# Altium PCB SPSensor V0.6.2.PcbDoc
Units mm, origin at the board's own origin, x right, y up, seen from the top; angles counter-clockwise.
Board outline 97.48 x 57.45 mm, 2 copper layers (TopLayer, BottomLayer), stack 1.671 mm thick; 103 components, 64 nets, 347 pads, 160 vias.
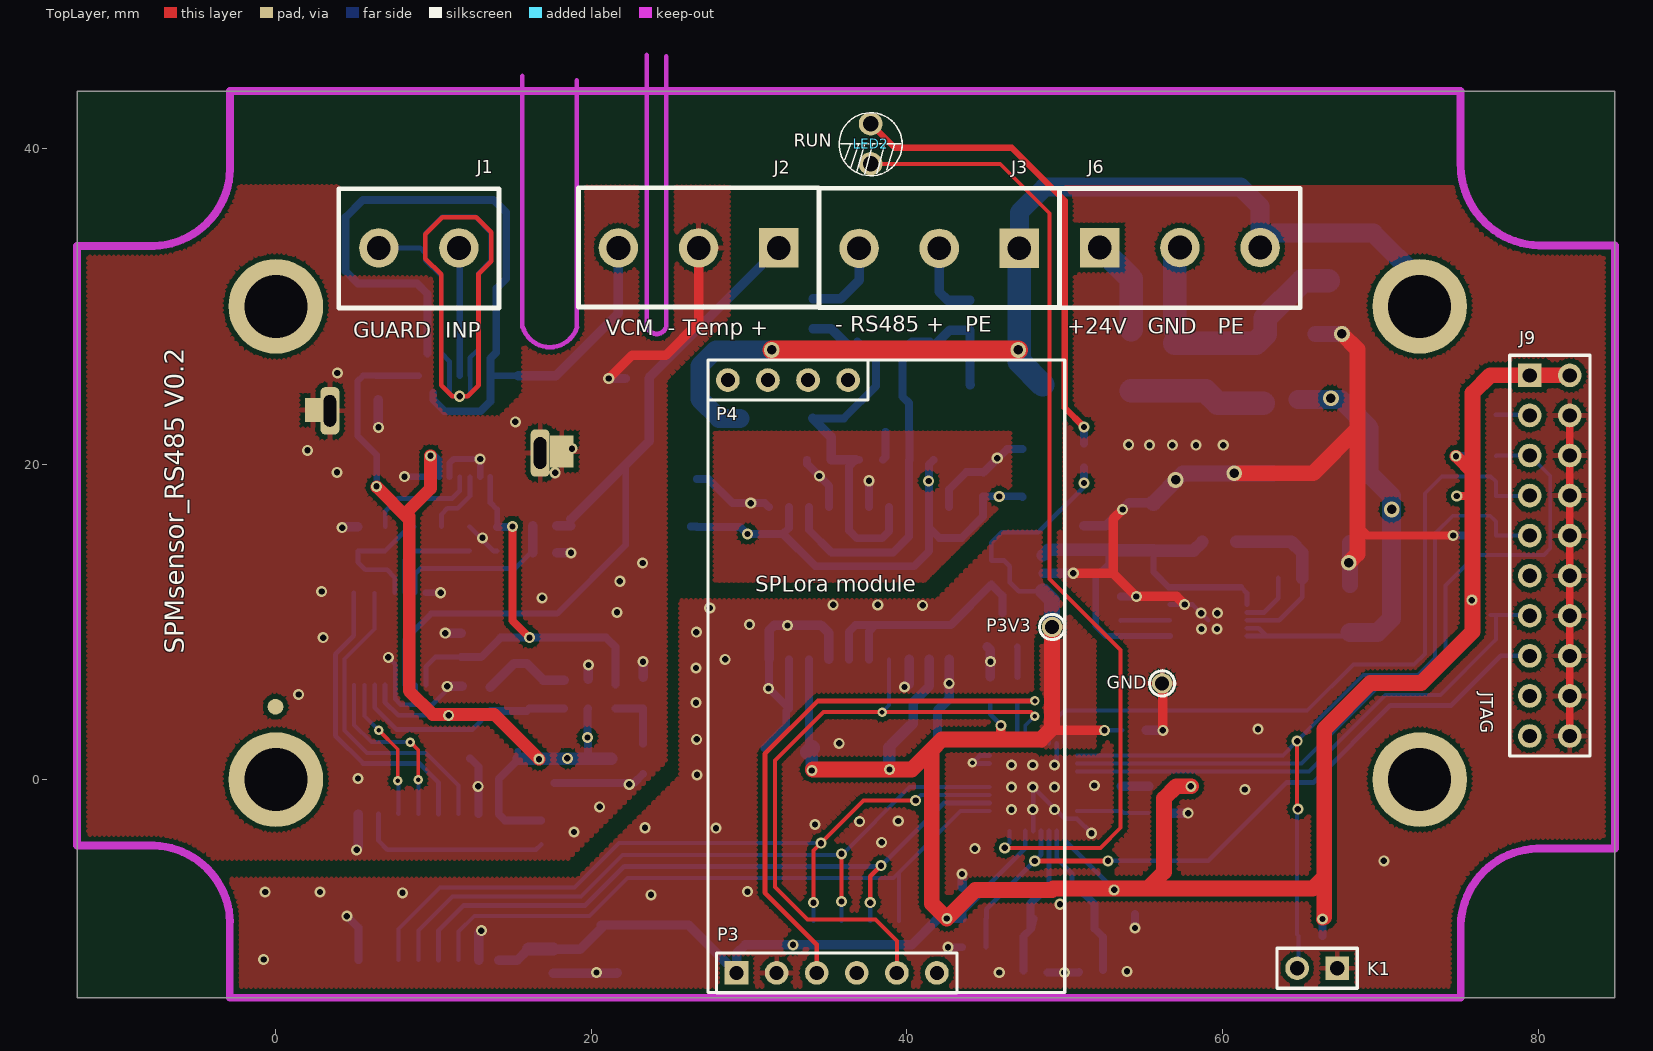
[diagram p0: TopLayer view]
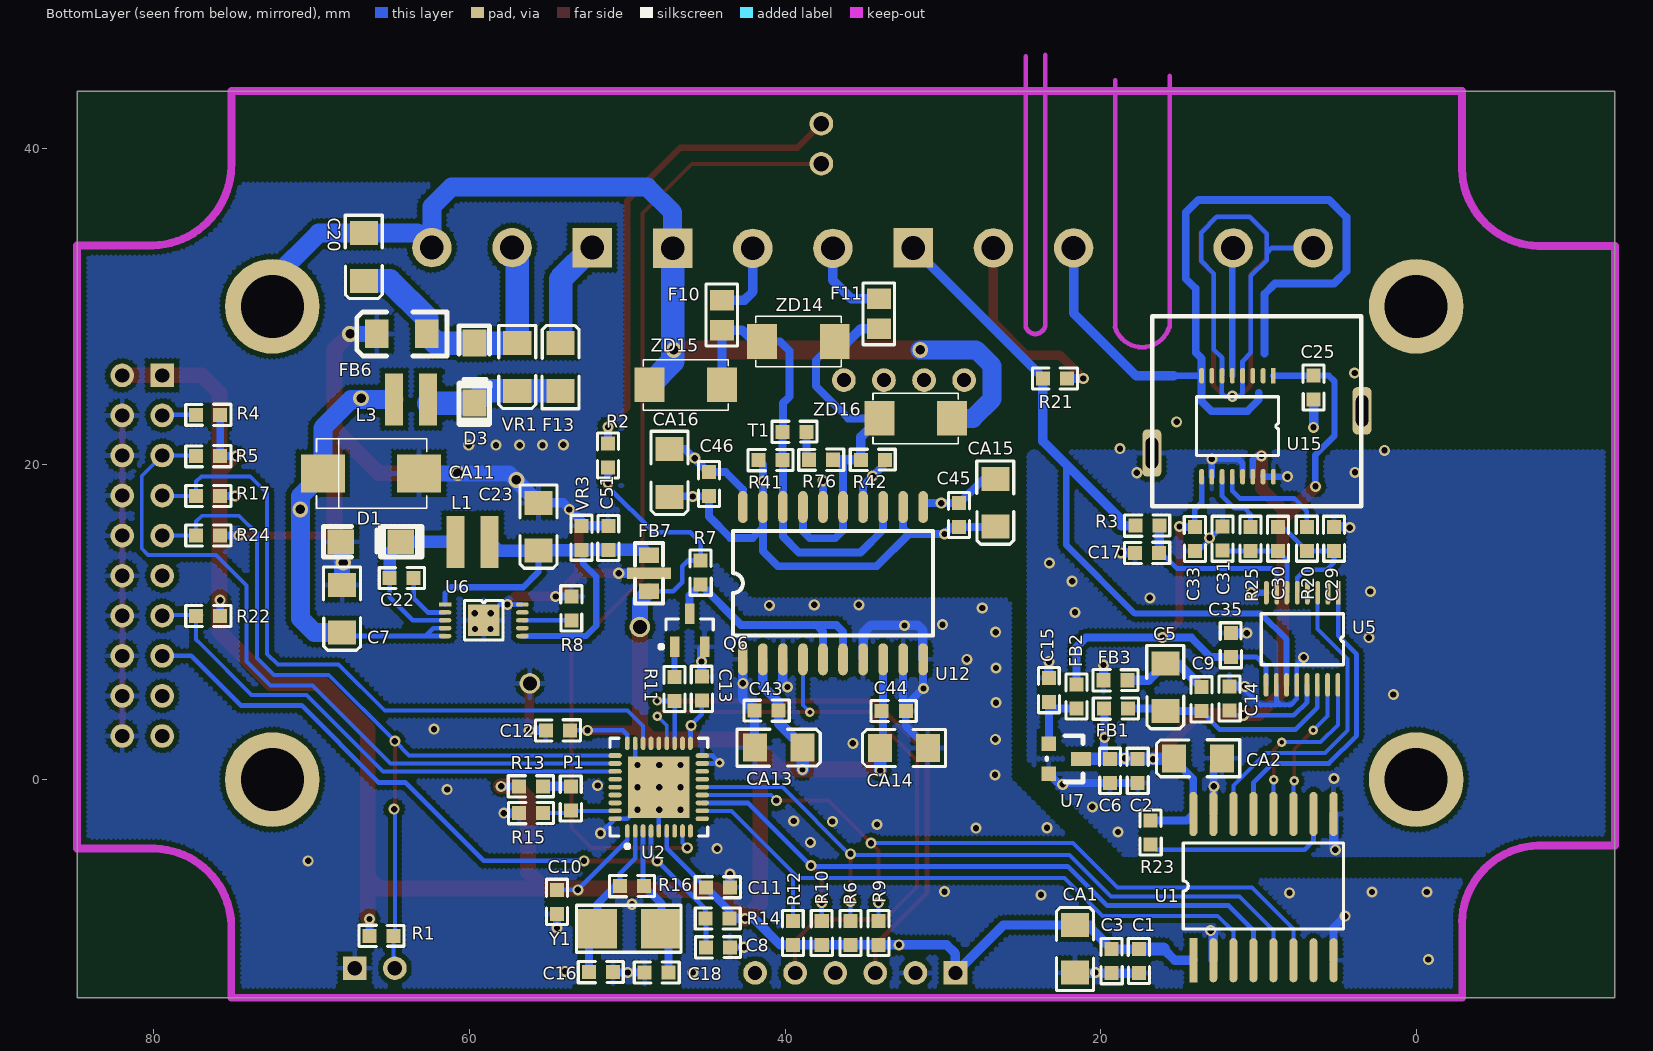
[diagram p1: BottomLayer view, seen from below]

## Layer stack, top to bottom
TopLayer: signal copper 0.0356
Dielectric: core 1.6, FR-4, Dk 4.8
BottomLayer: signal copper 0.0356

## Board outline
-12.6,-13.825 84.875,-13.825 84.875,43.625 -12.6,43.625

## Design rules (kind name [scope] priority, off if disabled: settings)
Clearance Clearance_poly [InPolygon] p1: gap=0.3
Clearance [All] p2: gap=0.15
ComponentClearance [All] p1: gap=0.15 collisioncheckmode=3 verticalgap=0.254 showdistances=FALSE
FabricationTestPointUsage TestPointUsage [All] p1: valid=0 allowmultiple=FALSE
FabricationTestpoint Testpoint [All] p1: side=3 testpointundercomponent=TRUE minsize=1.016 maxsize=2.54 preferedsize=1.524 minholesize=0.508 maxholesize=1.016 preferedholesize=0.813 testpointgrid=0.025 allowsidetop=TRUE allowsidebottom=TRUE usegrid=TRUE gridtolerance=0
HoleSize [All] p1: absolutevalues=TRUE maxlimit=10 minlimit=0.025 maxpercent=80.000 minpercent=20.000
MinimumSolderMaskSliver [All] p1: minsoldermaskwidth=0.15
PlaneClearance [All] p1: clearance=0.2
PlaneConnect [All] p1: planeconnectstyle=Relief reliefexpansion=0.3 reliefentries=4 reliefconductorwidth=0.3 reliefairgap=0.3
PolygonConnect PolygonConnect_via [IsVia] p1: connectstyle=Direct reliefconductorwidth=0.254 reliefentries=4 polygonreliefangle="90 Angle"
PolygonConnect [All] p2: connectstyle=Relief reliefconductorwidth=0.3 reliefentries=4 polygonreliefangle="90 Angle"
RoutingVias [All] p1: holewidth=0.305 width=0.61 viastyle="Through Hole" minholewidth=0.254 minwidth=0.508 maxholewidth=2 maxwidth=5
SilkToSilkClearance [All] p1: silktosilkclearance=0
SilkscreenOverComponentPads [All] p1: minsilkscreentomaskgap=0
SolderMaskExpansion [All] p1: expansion=0.102
Width [All] p1: maxlimit=5.08 minlimit=0.1 preferedwidth=0.254
19 further rules are at their usual default settings.

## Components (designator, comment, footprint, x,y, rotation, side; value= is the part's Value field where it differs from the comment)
C1 "10nF" SM0603 17.525,-11.5 r270 bottom
C2 "0.1uF" SM0603 17.6,0.55 r270 bottom
C3 "0.1uF" SM0603 19.35,-11.5 r90 bottom
C5 "10uF" SM1206 15.9,5.85 r270 bottom
C6 "4.7uF" SM0603 19.35,0.55 r270 bottom
C7 "4.7uF/50V" SM1206 68.075,10.825 r270 bottom
C8 "0.1uF" SM0603 44.25,-10.575 r180 bottom
C9 "0.1uF" SM0603 13.65,5.1 r90 bottom
C10 "0.1uF" SM0603 54.405,-7.75 r270 bottom
C11 "0.1uF" SM0603 44.255,-6.775 r180 bottom
C12 "0.1uF" SM0603 54.4,3.075 r0 bottom
C13 "0.1uF" SM0603 45.33,5.765 r90 bottom
C14 "0.1uF" SM0603 11.875,5.15 r90 bottom
C15 "1uF" SM0603 23.325,5.675 r90 bottom
C16 "22pF" SM0603 51.675,-12.15 r180 bottom
C17 "1uF" SM0603 17.055,14.325 r0 bottom
C18 "22pF" SM0603 48.14,-12.275 r0 bottom
C20 "1nF/2kV" SM1206 66.7,33.125 r270 bottom
C22 "0.47uF" SM0603 64.3,12.725 r0 bottom
C23 "22uF" SM1206 55.625,16.025 r270 bottom
C25 "0.1uF" SM0603 6.45,24.85 r270 bottom
C29 "1uF" SM0603 5.15,15.26 r270 bottom
C30 "100pF" SM0603 8.7,15.26 r270 bottom
C31 "1uF" SM0603 12.325,15.275 r90 bottom
C33 "0.1uF" SM0603 13.975,15.25 r270 bottom
C35 "0.1uF" SM0603 11.8,8.525 r90 bottom
C43 "0.1uF" SM0603 41.175,4.325 r0 bottom
C44 "0.1uF" SM0603 33.11,4.4 r180 bottom
C45 "0.1uF" SM0603 29.025,16.775 r90 bottom
C46 "0.1uF" SM0603 44.775,18.725 r270 bottom
C51 "0.1uF" SM0603 51.25,15.325 r90 bottom
CA1 "10uF" SM1206 21.625,-10.725 r90 bottom
CA2 "10uF" SM1206 13.825,1.35 r0 bottom
CA11 "47uF/50V" D 69.3,19.4 r180 bottom
CA13 "10uF" SM1206 40.4,2.025 r180 bottom
CA14 "10uF" SM1206 32.465,2 r0 bottom
CA15 "10uF" SM1206 26.675,17.55 r270 bottom
CA16 "10uF" SM1206 47.325,19.435 r270 bottom
D1 "CD1607-B140" 1206D 67.967,15.075 r180 bottom
D3 "1N4007" 1206D 59.7,27.475 r270 bottom
F10 "FUSE1" SM0805 43.975,29.425 r90 bottom
F11 "FUSE1" SM0805 34.025,29.5 r90 bottom
F13 "1A" SM1206 54.225,26.15 r90 bottom
FB1 "BLM18PG600SN1" SM0603 19.025,4.55 r180 bottom
FB2 "BLM18PG600SN1" SM0603 21.575,5.275 r90 bottom
FB3 "BLM18PG600SN1" SM0603 19.05,6.35 r180 bottom
FB6 "BLM31PG500SN1" 1206 65.75,28.25 r0 bottom
FB7 "NFM21PC105B1C3" NFM21PC105 48.625,14.225 r270 bottom
GND "TestPoint" "test point" 56.175,6.1 r90 top
J1 "PH2-5.08mm" PH2-5.08mm 6.525,33.7 r0 top
J2 "PH3-5.08mm" PH3-5.08mm 31.875,33.7 r180 top
J3 "PH3-5.08mm" PH3-5.08mm 47.125,33.675 r180 top
J6 "PH3-5.08mm" PH3-5.08mm 52.225,33.725 r0 top
J9 "JTAG" HDR2X10 79.475,25.625 r270 top
K1 "KEY1" HDR1x2 67.275,-11.955 r180 top (schematic designator R1)
L1 "LPS3010-472ML" LPS3010 60.885,15.075 r180 bottom
L3 "LPS3010-472ML" LPS3010 62.625,24.1 r0 bottom
LED2 "RUN" LED 37.7,41.575 r270 top
P1 "NC" sm0603 53.63,-1.185 r90 bottom
P3 "Header 6" HDR1X6 29.2,-12.25 r0 top
P3V3 "TestPoint" "test point" 49.2,9.675 r90 top
P4 "Lora module" HDR1X4 28.65,25.325 r0 top
Q6 "MMBT3904" SOT23_N 46.05,9.475 r90 bottom
R1 "10K" SM0603 65.575,-9.855 r180 bottom
R2 "560R" SM0603 51.275,20.55 r90 bottom
R3 "10K" SM0603 17.04,16.15 r180 bottom
R4 "10K" SM0603 76.565,23.075 r0 bottom
R5 "10K" SM0603 76.565,20.45 r0 bottom
R6 "100K" SM0603 35.901,-9.713 r90 bottom
R7 "4.7K" SM0603 45.4,13.125 r90 bottom
R8 "49.9K" SM0603 53.5,10.85 r270 bottom
R9 "100K" SM0603 34.126,-9.713 r90 bottom
R10 "100K" SM0603 37.726,-9.713 r90 bottom
R11 "1K" SM0603 47.055,5.75 r90 bottom
R12 "100K" SM0603 39.551,-9.713 r90 bottom
R13 "1K" SM0603 56.105,-0.375 r180 bottom
R14 "10K" SM0603 44.275,-8.85 r0 bottom
R15 "100K" SM0603 56.09,-2.075 r180 bottom
R16 "10M" SM0603 49.7,-6.7 r180 bottom
R17 "10K" SM0603 76.565,17.925 r0 bottom
R20 "10K" SM0603 6.875,15.26 r270 bottom
R21 "NC" SM0603 22.9,25.375 r0 bottom
R22 "10K" SM0603 76.565,10.325 r0 bottom
R23 "4.7K" SM0603 16.875,-3.35 r90 bottom
R24 "NC" SM0603 76.565,15.425 r0 bottom
R25 "10K" SM0603 10.45,15.26 r270 bottom
R41 "47K" SM0603 40.91,20.3 r180 bottom
R42 "47K" SM0603 34.435,20.325 r180 bottom
R76 "120R" SM0603 37.715,20.225 r0 bottom
T1 "" SM0603 39.4,22.1 r180 bottom
U1 "ADuM5401ARWZ" ADUM1401 14.125,-11.45 r90 bottom
U2 "STM32F103TBU6" VFQN36_V 48,-0.475 r90 bottom locked
U5 "AD7793BRU" AD7793 7.225,8.925 r270 bottom
U6 "LT3971IMSE-3.3" LT3971 59.1,10.1 r270 bottom
U7 "AD1584BRTZ" SOT-23 21.13,-0.061 r270 bottom
U12 "ADM2587E" SOL-20 42.675,7.625 r90 bottom
U15 "LMP91200" LMP91200 11.325,22.4 r0 bottom
VR1 "V42MLA1206N" SM1206 56.975,26.15 r270 bottom
VR3 "V3.5MLA0603N" SM0603 52.85,15.325 r270 bottom (schematic designator VA2)
Y1 "8MHz" CY5.4X4.6 51.875,-9.45 r180 bottom
ZD14 "SMBJ12" ZD 41.45,27.775 r180 bottom
ZD15 "SMBJ12" ZD 44,25.025 r0 bottom
ZD16 "SMBJ12" ZD 29.425,22.9 r0 bottom

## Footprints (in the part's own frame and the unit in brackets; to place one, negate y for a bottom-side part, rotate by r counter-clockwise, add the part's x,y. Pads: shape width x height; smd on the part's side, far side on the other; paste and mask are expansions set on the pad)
1206 [mm]
  rect 1.5x1.8 smd: 1(-3.048,0) 2(0.127,0)
  silkscreen extent -4.32,-1.4 1.4,1.4
1206D [mm]
  rect 1.7x1.524 smd: 1(-0.19,0.003) 2(3.61,0.003)
  silkscreen extent -1.3,-0.97 4.96,0.99
AD7793 [mm]
  rect 1.5x0.3 smd: 1(-2.921,2.286)
  oval 1.5x0.3 smd: 2(-2.921,1.636) 3(-2.921,0.986) 4(-2.921,0.336) 5(-2.921,-0.314) 6(-2.921,-0.964) 7(-2.921,-1.614) 8(-2.921,-2.264) 9(2.921,-2.286) 10(2.921,-1.636) 11(2.921,-0.986) 12(2.921,-0.336) 13(2.921,0.314) 14(2.921,0.964) 15(2.921,1.614) 16(2.921,2.264)
  silkscreen extent -1.59,-2.59 1.64,2.61
ADUM1401 [mm]
  rect 2.8x0.51 smd: 1(0,0)
  oval 2.8x0.51 smd: 2(0,-1.27) 3(0,-2.54) 4(0,-3.81) 5(0,-5.08) 6(0,-6.35) 7(0,-7.62) 8(0,-8.89) 9(9.271,-8.89) 10(9.271,-7.62) 11(9.271,-6.35) 12(9.271,-5.08) 13(9.271,-3.81) 14(9.271,-2.54) 15(9.271,-1.27) 16(9.271,0)
  silkscreen extent 1.99,-9.53 7.43,0.63
CY5.4X4.6 [mm]
  rect 2.5x2.5 smd: 1(-0.025,0) 2(4,0)
  silkscreen extent -1.35,-1.49 5.28,1.49
D [mil]
  rect 110x94.49 smd: 1(0,0) 2(240,0)
  silkscreen extent -16,-87 260,87
HDR1x2 [mm] "Connector; Header; 2 Position"
  rect 1.5x1.5 hole 0.9: 1(0,0)
  round 1.5 hole 0.9: 2(2.54,0)
  silkscreen extent -1.27,-1.27 3.81,1.27
HDR1X4 [mm] "Connector; Header; 4 Position"
  round 1.5 hole 0.9: 1(0,0) 2(2.54,0) 3(5.08,0) 4(7.62,0)
  silkscreen extent -1.27,-1.27 8.89,1.27
HDR1X6 [mm] "Connector; Header; 6 Position"
  rect 1.5x1.5 hole 0.9: 1(0,0)
  round 1.5 hole 0.9: 2(2.54,0) 3(5.08,0) 4(7.62,0) 5(10.16,0) 6(12.7,0)
  silkscreen extent -1.27,-1.27 13.97,1.27
HDR2X10 [mm] "Connector; Header; 10x2 Position"
  rect 1.5x1.5 hole 0.9: 1(0,0)
  round 1.5 hole 0.9: 2(0,2.54) 3(2.54,0) 4(2.54,2.54) 5(5.08,0) 6(5.08,2.54) 7(7.62,0) 8(7.62,2.54) 9(10.16,0) 10(10.16,2.54) 11(12.7,0) 12(12.7,2.54) 13(15.24,0) 14(15.24,2.54) 15(17.78,0) 16(17.78,2.54) 17(20.32,0) 18(20.32,2.54) 19(22.86,0) 20(22.86,2.54)
  silkscreen extent -1.27,-1.27 24.13,3.81
LED [mm]
  round 1.5 hole 1: 1(0,0) 2(2.54,0)
  silkscreen extent -0.7,-2 3.3,2
LMP91200 [mm]
  rect 0.3x1 smd: 1(-2.275,-3.2)
  oval 0.3x1 smd: 2(-1.625,-3.2) 3(-0.975,-3.2) 4(-0.325,-3.2) 5(0.325,-3.2) 6(0.975,-3.2) 7(1.625,-3.2) 8(2.275,-3.2) 9(2.275,3.2) 10(1.625,3.2) 11(0.975,3.2) 12(0.325,3.2) 13(-0.325,3.2) 14(-0.975,3.2) 15(-1.625,3.2) 16(-2.275,3.2)
  silkscreen extent -2.6,-1.87 2.6,1.87
LPS3010 [mm]
  rect 1.14x3.3 smd: 1(0,0) 2(2.16,0)
LT3971 [mm]
  rect 0.28x0.8 smd: 1(-1,-2.45)
  oval 0.28x0.8 smd: 2(-0.5,-2.45) 3(0,-2.45) 4(0.5,-2.45) 5(1,-2.45) 6(1,2.45) 7(0.5,2.45) 8(0,2.45) 9(-0.5,2.45) 10(-1,2.45)
  rect 2x2 smd: 11(0,0)
  silkscreen extent -1.25,-1.21 1.25,1.22
NFM21PC105 [mm]
  rect 1x1.27 smd: 1(0.01,0.008) 2(2.286,0)
  rect 0.7x2.8 smd: 3(1.143,0)
  silkscreen extent -0.76,-0.89 3.05,0.89
PH2-5.08mm [mm]
  round 2.5 hole 1.5: 1(0,0) 2(5.08,0)
  silkscreen extent -2.54,-3.81 7.62,3.75
PH3-5.08mm [mm]
  rect 2.5x2.5 hole 1.5: 1(0,0)
  round 2.5 hole 1.5: 2(5.08,0) 3(10.16,0)
  silkscreen extent -2.54,-3.81 12.7,3.75
SM0603 [mil]
  rect 35x35 smd: 1(-30,-2) 2(30,-2)
  silkscreen extent -57,-28 56,24
sm0603 [mil]
  rect 35x35 smd: 1(-30,-2) 2(30,-2)
  silkscreen extent -57,-28 56,24
SM0805 [mm]
  rect 1.3x1.5 smd: 1(-0.933,0.022) 2(0.967,0.022)
  silkscreen extent -1.93,-0.97 1.98,1.04
SM1206 [mil]
  rect 60x70 smd: 1(59.5,0) 2(-59.5,0)
  silkscreen extent -104,-46 104,46
SOL-20 [mil]
  oval 80x24 smd: 1(0,0) 2(0,-50) 3(0,-100) 4(0,-150) 5(0,-200) 6(0,-250) 7(0,-300) 8(0,-350) 9(0,-400) 10(0,-450) 11(380,-450) 12(380,-400) 13(380,-350) 14(380,-300) 15(380,-250) 16(380,-200) 17(380,-150) 18(380,-100) 19(380,-50) 20(380,0)
  silkscreen extent 60,-475 320,25
SOT23_N [mm] "SOT23, 3-Leads, Body 2.9x1.3mm, Pitch 0.95mm, Lead Span 2.3mm, IPC Medium Density"
  rect 1.3x0.6 smd: 1(-1.05,0.95) 2(-1.05,-0.95) 3(1.05,0)
  silkscreen extent -1.17,-1.5 0.7,1.93, body extent -0.7,-1.5 0.7,1.5, height 1.1
SOT-23 [mil]
  rect 36x36 smd: 1(-91.86,-84.66) 2(-16.86,-84.66)
  rect 36x50 smd: 3(-53.86,-4.66)
  silkscreen extent -112,-90 3,0
"test point" [mm]
  round 1.3 hole 0.9: 1(0,0)
  silkscreen extent -0.8,-0.8 0.8,0.8
VFQN36_V [mm] "QFN, 36-Leads, Body 6x6mm, Pitch 0.5mm, ST Recommended"
  oval 0.85x0.3 smd: 1(-2.775,2) 2(-2.775,1.5) 3(-2.775,1) 4(-2.775,0.5) 5(-2.775,0) 6(-2.775,-0.5) 7(-2.775,-1) 8(-2.775,-1.5) 9(-2.775,-2) 19(2.775,-2) 20(2.775,-1.5) 21(2.775,-1) 22(2.775,-0.5) 23(2.775,0) 24(2.775,0.5) 25(2.775,1) 26(2.775,1.5) 27(2.775,2)
  oval 0.3x0.85 smd: 10(-2,-2.755) 11(-1.5,-2.755) 12(-1,-2.755) 13(-0.5,-2.755) 14(0,-2.755) 15(0.5,-2.755) 16(1,-2.755) 17(1.5,-2.755) 18(2,-2.755) 28(2,2.775) 29(1.5,2.775) 30(1,2.775) 31(0.5,2.775) 32(0,2.775) 33(-0.5,2.775) 34(-1,2.775) 35(-1.5,2.775) 36(-2,2.775)
  rect 3.9x3.9 smd: 37(0,0)
  silkscreen extent -3.87,-3.1 3.1,3.1, body extent -3.05,-3.05 3.05,3.05, height 1
ZD [mm]
  rect 1.9x2.2 smd: 1(0,0) 2(4.6,0)
  silkscreen extent -0.4,-1.6 5,1.6

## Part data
C1 C6 C7 C9 C14 C15 C17 C20 C22 C25 C29 C30 C31 C33 C35 C51: library part CAP, "Capacitor"
C2 C3 C43 C44 C45 C46: library part C, "电?"
C5 CA11 CA13 CA14 CA15 CA16: library part CAPE, "极?"
C8: library part Cap, "Capacitor, X7R Ceramic"
C10 C11 C12 C13 C16 C18: library part Cap, "Capacitor"
C23: library part C, "极?"
CA1 CA2: library part CAPE, "Capacitor"
D1: library part DIODE, "Diode"
D3: library part "Diode 1N4007", "1 Amp General Purpose Rectifier"
F10 F11: "Fuse"
F13: library part FUSE1, "Fuse"
FB1 FB3 L1 L3: library part INDUCTOR
FB2 FB6 FB7: library part Inductor, "Inductor"
J1 K1: library part "Header 2", "Header, 2-Pin"
J2 J3 J6: library part CON3, "Connector"
J9: library part "Header 10X2", "Header, 10-Pin, Dual row"
LED2: library part LED0, "Typical INFRARED GaAs LED"
P1: library part H, "Header, 2-Pin, 2.54mm, 排?"
P3: "Header, 6-Pin"
P4: library part "Header 4", "Header, 4-Pin"
Q6: "NPN Switching Transistor"
R1 R2 R7 R11 R16: library part Res2, "Resistor"
R3 R4 R5 R6 R9 R10 R12 R17 R20 R21 R22 R24 R25: library part RE, "电?"
R8 R13 R14 R15 R23 R41 R42 R76: library part R, "电?"
T1: library part CON2, "Connector"
U1: library part ADUM1401, "1Mbps Data Rate, 100ns Propagation delay"
U2: library part STM32F103T8U6, "STM32 ARM-based 32-bit MCU with 64 Kbytes Flash, 36-pin VFQFPN, Industrial Temperature"
U5: library part AD7793
U6: library part LT3971
U7: library part "Header 3", "4.096V reference"
VR1: library part "Res Varistor", "Varistor (Voltage-Sensitive Resistor)"
VR3: library part "D Zener", "Zener Diode"
Y1: library part XTAL, "Crystal Oscillator"
ZD14 ZD15 ZD16: library part SMBJ, "˲?"

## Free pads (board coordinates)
  round 1 smd: 0(-0.025,4.625)
  rrect50% 1.2x3 hole 0.8 slot 2 at 90 deg: 0(3.425,23.375) 0(16.75,20.7)
  rect 1x1.5 smd: 1(2.35,23.425)
  rect 1.5x2 smd: 1(18.125,20.8)
  round 6 hole 4: 3(72.5,30) 4(72.5,0) 5(0,0) 6(0,30)

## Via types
v1: diameter 0.7, hole 0.4, TopLayer to BottomLayer, 144 vias
v2: diameter 1, hole 0.6, TopLayer to BottomLayer, 8 vias
v3: diameter 0.6, hole 0.3, TopLayer to BottomLayer, 8 vias

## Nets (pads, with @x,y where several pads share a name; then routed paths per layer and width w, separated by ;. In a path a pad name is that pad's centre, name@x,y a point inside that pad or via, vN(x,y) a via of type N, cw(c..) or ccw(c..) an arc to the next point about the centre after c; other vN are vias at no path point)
24VGND_IN: C20.1 D3.1 FB6.1 J6.2 VR1.2 | length 17.8
  BottomLayer w1.5: VR1.2 59.693,27.661 D3.1 62.117,27.665 FB6.1 62.702,29.252 65.064,31.614 C20.1 ; 56.975,28.536 56.975,33.395 J6.2 J6.2@57.647,33.383
+24V: C7.1 CA11.1 L3.2 U6.4 U6.5 | length 29
  BottomLayer w0.3: U6.5 62.8,9.1 ; U6.4 62.3,9.6 62.8,9.1 ; C7.1 67.861,9.1 62.8,9.1
  BottomLayer w1.2: L3.2 67.5,24.1 69.3,22.3 CA11.1 70.725,17.975 70.725,10.225 69.814,9.314 C7.1
  other v2: 70.725,17.125 66.875,24.175
+24V_IN: F13.1 J6.1 | length 6.1
  BottomLayer w1.5: J6.1@52.175,33.675 J6.1 54.225,31.725 54.225,28.536
BOOT0: P1.1 R15.2 U2.35 | length 4.6
  BottomLayer w0.25: U2.35 53.552,-1.975 P1.1 53.758,-2.126 R15.2
DE485: Q6.3 R7.1 U12.5 U12.6 | length 16.5
  BottomLayer w0.5: U12.6 36.325,9.375 36.75,9.8 38,9.8 ; U12.5 37.595,9.395 38,9.8 ; Q6.3 46.05,11.662 R7.1 42.786,9.8 38,9.8
DVDD: C5.1 C9.1 FB1.2 U5.14 | length 14.6
  BottomLayer w0.3: U5.14 6.261,4.564 7.65,3.175 12.436,3.175 C9.1
  BottomLayer w0.5: C9.1 C5.1@15.899,4.338 ; C5.1 16.061,4.499 FB1.2
EARTH: C20.2 J3.1 J6.3 pad.3 ZD15.2 ZD16.1 | length 69.8
  TopLayer w1.2: v2(31.438,27.237) v2(47.062,27.237)
  BottomLayer w1.2: ZD16.1 28.1,22.9 26.875,24.125 26.875,26.225 27.887,27.237 v2(31.438,27.237) ; J3.1 47.125,35.95 48.725,37.55 61.15,37.55 62.385,36.315 J6.3 63.296,34.636 C20.2 69.564,34.636 72.5,31.7 pad.3
  BottomLayer w1.5: J3.1@47.175,33.625 J3.1 47.125,26.5 ZD15.2
GND: C1.2 C3.1 C7.2 C8.2 C10.2 C11.2 C12.2 C13.2 C16.2 C18.2 C23.2 C43.2 C44.2 C51.2 CA1.2 CA11.2 CA13.2 CA14.2 D1.1 FB6.2 FB7.3 GND.1 J9.4 J9.6 J9.8 J9.10 J9.12 J9.14 J9.16 J9.18 J9.20 K1.1 P3.2 Q6.2 R8.1 R15.1 R24.1 U1.2 U1.8 U2.5 U2.17 U2.18 U2.26 U2.36 U2.37 U6.10 U6.11 U12.1 U12.3 U12.7 U12.9 U12.10 VR3.1 | length 145.1
  TopLayer w0.3: v1@51.85,-0.375 v1(51.875,-0.375)
  TopLayer w0.5: 68.55,16.125 69.199,15.476 v1(74.625,15.476) ; J9.20 J9.18 J9.16 J9.14 J9.12 J9.10 J9.8 J9.6 J9.4
  TopLayer w0.6: v1(50.543,13.082) 53.068,13.082 ; v1(53.675,17.125) 53.068,16.518 53.068,13.082 ; GND.1 56.224,6.051 v1(56.224,3.126) ; v1(57.6,11.1) 57.088,11.612 v1(54.538,11.612) 53.068,13.082
  TopLayer w1: v2(60.75,19.425) 65.75,19.425 68.55,22.225 ; v2(67.575,28.25) 68.55,27.275 68.55,22.225 ; v2(68,13.75) 68.55,14.3 68.55,16.125 68.55,22.225
  BottomLayer w0.3: U2.17 44.2,1.025 v3(44.15,1.075) 44.6,1.525 U2.18 ; U2.5 U2.37 50,-2.475 U2.36 v1(51.7,-3.4) ; U2.37@49.5,1.025 U2.26 ; U6.10 58.1,11.1 U6.11
  BottomLayer w0.5: v1(4.5,-8.65) 5.235,-9.385 U1.8 ; CA14.2 32.348,3.395 C44.2 C44.2@32.515,4.516 ; U12.10 31.245,5.786 C44.2@32.515,4.516 ; U12.9 C44.2@32.515,4.516 ; v1(42.601,-10.626) C8.2 ; C18.2 v1(49.975,-12.224) 50.89,-12.224 C16.2 ; R8.1 v1(54.538,11.612) ; v1(54.456,-9.406) C10.2 ; v1(74.625,15.476) R24.1
  BottomLayer w0.6: U1.2 12.855,-9.745 v1(13.025,-9.575) ; C1.2 21.599,-12.262 CA1.2 ; U12.10@31.265,7.625 31.265,9.465 31.6,9.8 34.55,9.8 35.055,9.295 U12.7 ; v1(39.85,5.875) 39.95,5.875 40.135,6.06 U12.3 ; CA13.2 41.937,2.05 C43.2 42.675,5.114 U12.1 ; C11.2 v1(43.493,-5.982) ; Q6.2 45.279,8.246 C13.2 ; FB7.3 v1(50.543,13.082) ; C51.2 52.612,16.087 54.061,17.536 C23.2 ; C12.2 v1(56.224,3.126) ; R15.1 v1(57.826,-2.126)
  BottomLayer w1: C23.2 57.489,19.4 CA11.2 ; FB6.2 v2(67.575,28.25) ; C7.2 D1.1@68.075,14.995
  other v1: 20.325,-12.225 45.85,-12.225 53.95,-12.15 -0.775,-11.4 49.7,-7.9 23.775,-7.3 8.025,-7.175 -0.681,-7.125 2.8,-7.125 29.9,-7.1 70.225,-5.15 44.3,-4.375 38.4,-3.975 27.9,-3.075 23.4,-3.05 34.175,-2.85 37,-2.65 39.45,-2.625 46.625,-1.9 47.975,-1.9 49.35,-1.9 61.419,-0.625 46.625,-0.475 47.975,-0.475 49.35,-0.475 26.694,0.3 46.625,0.925 47.975,0.925 49.35,0.925 35.7,2.3 26.675,2.55 62.25,3.2 26.625,4.875 31.225,5.775 42.675,6.1 26.625,7.075 45.3,7.475 28.475,7.625 26.65,9.35 58.675,9.55 59.65,9.55 32.425,9.775 30.025,9.825 58.65,10.55 59.675,10.55 27.5,10.875 41,11.05 35.325,11.075 38.15,11.075 55.375,21.2 56.825,21.2 58.325,21.2 60.05,21.2 54.05,21.225
  other v2: 57.025,19
GND_COM: C45.2 C46.1 CA15.2 CA16.2 R42.2 U12.11 U12.14 U12.16 U12.20 | length 17.4
  BottomLayer w0.5: CA15.2 27.414,19.061 28.938,17.537 30.985,17.537 U12.11 ; R42.2 33.673,20.002 35.055,18.62 U12.14 ; U12.16 v1(37.595,18.945) ; U12.20 42.675,18.4 43.762,19.487 C46.1 ; C46.1@44.851,19.462 46.336,20.947 CA16.2
  other v1: 30.1,17.525 34.45,19.25 45.725,20.375
GND_ISO: C2.2 C6.2 C14.2 C15.2 C17.2 C25.2 C29.1 C31.2 C33.2 C35.2 CA2.2 FB3.1 J2.2 pad.0@3.425,23.375 pad.0@16.75,20.7 pad.1 R21.1 U1.9 U1.15 U5.8 U5.10 U5.12 U7.2 U15.10 U15.13 U15.15 U15.16 | length 49.6
  TopLayer w0.6: v1(21.1,25.425) 22.576,26.901 24.726,26.901 26.795,28.97 J2.2
  BottomLayer w0.3: v1(7.125,7.75) 7.561,7.314 U5.12 7.561,5.114 7.925,4.75 8.625,4.75 ; U5.10 8.861,4.986 8.625,4.75 ; v1(10.862,5.912) 10.862,5.687 9.925,4.75 8.625,4.75 ; C31.2 13.823,14.488 C33.2
  BottomLayer w0.4: v1(8.15,19.2) U15.16 U15.15 ; U5.8 v1(10.446,11.846) ; U15.13 11,20.05 11.275,20.325 v1(12.95,20.325) U15.10
  BottomLayer w0.5: CA2.2 12.855,0.809 U1.15 ; C2.2 C6.2 22.702,-0.212 U7.2
  BottomLayer w0.6: v1(4.2,15.975) 4.247,16.022 C29.1 ; v1(5.125,-4.45) 5.235,-4.34 U1.9 ; v1(6.501,22.326) C25.2 ; v1(10.737,9.287) C35.2 ; v1(10.862,5.912) C14.2 ; C17.2 v1(18.701,14.376) ; FB3.1@19.812,6.374 v1(19.812,7.262) ; v1(21.1,25.425) R21.1@22.138,25.425 ; C15.2@23.274,6.487 23.274,6.887 v1(23.274,7.474)
  other v1: 18.9,-3.325 20.525,-1.725 12.825,-0.425 22.4,-0.3 5.2,0.075 1.444,5.4 3,9 21.625,10.6 16.875,11.525 2.9,11.925 21.8,12.575 23.25,13.725 13.1,15.325 17.7,19.45 3.875,19.475 2,20.875 18.775,20.975 15.175,22.675 3.9,25.775
GUARD: J1.1 U15.4 U15.6 | length 59
  TopLayer w0.3: 9.475,33.025 9.475,34.575 10.55,35.65 12.7,35.65 13.65,34.7 13.65,32.85 12.85,32.05 12.85,25 12.15,24.3 v1(11.65,24.3) 11.175,24.3 10.475,25 10.475,32.025 9.475,33.025
  BottomLayer w0.3: J1.1 9.15,33.7 9.475,33.375 ; U15.6 12.3,26.725 12.825,27.25 12.825,32.075 13.625,32.875 13.625,34.675 12.625,35.675 10.55,35.675 9.475,34.6 9.475,33.375 ; U15.6@12.325,25.6 12.325,24.5 12.125,24.3 v1(11.65,24.3) 11.2,24.3 11,24.5 U15.4 11,26.525 10.475,27.05 10.475,31.925 9.475,32.925 9.475,33.375
JNTRST: J9.3 R4.2 | length 2.2
  BottomLayer w0.3: R4.2 79.434,23.126 J9.3
JTCK: J9.9 K1.2 R1.2 R24.2 U2.28 | length 55.1
  TopLayer w0.25: v1(64.735,2.435) 64.735,-1.835 v1(64.775,-1.875)
  BottomLayer w0.25: U2.28 63.825,1.525 v1(64.735,2.435) 68.925,6.625 72.4,6.625 73.475,7.7 73.475,15.6 74.6,16.725 76.95,16.725 77.327,16.348 R24.2 77.338,15.465 J9.9 ; K1.2 64.813,-11.877 R1.2 64.735,-9.828 v1@64.735,-1.875
JTDI: J9.5 R5.2 U2.29 | length 47.1
  BottomLayer w0.25: U2.29 65,1.025 69.95,5.975 72.625,5.975 74.125,7.475 74.125,12.3 76.075,14.25 80.375,14.25 80.775,14.65 80.775,19.245 J9.5 77.371,20.545 R5.2
JTDO: J9.13 R22.2 U2.30 | length 34
  BottomLayer w0.25: U2.30 65.475,0.525 70.325,5.375 73.827,5.375 77.002,8.55 77.327,8.875 R22.2 ; R22.2@77.002,10.426 79.434,10.426 J9.13
JTMS: J9.7 R17.2 U2.25 | length 45.2
  BottomLayer w0.25: U2.25 49,3.4 49.975,4.375 65.375,4.375 68.3,7.3 72.15,7.3 72.825,7.975 72.825,18.15 73.9,19.225 77,19.225 77.327,18.898 R17.2 79.446,17.976 J9.7
JTRST: U2.31
KEY1: U2.24
LED_S1: U2.23
LED_S2: LED2.2 U2.8 | length 62.5
  TopLayer w0.25: LED2.2 45.915,39.035 49.05,35.9 49.05,12.725 53.55,8.225 53.55,-3.05 52.275,-4.325 v1(46.2,-4.325)
  BottomLayer w0.25: v1(46.2,-4.325) 46.5,-4.025 U2.8
LORA_AUX: P3.6
MCU_RXD1: P3.5 U2.22 U12.4 | length 42.5
  TopLayer w0.25: P3.5 39.36,-10.235 38,-8.875 33.7,-8.875 31.625,-6.8 31.625,1.2 34.7,4.275 47.85,4.275 v3(48.1,4.025)
  BottomLayer w0.25: v3(38.425,4.275) 38.865,4.715 U12.4 ; U2.22 47.5,3.425 v3(48.1,4.025)
MCU_TXD1: P3.3 R11.1 U2.21 | length 37.5
  TopLayer w0.3: P3.3 34.28,-10.455 31,-7.175 31,1.625 34.363,4.988 v3(48.113,4.988)
  BottomLayer w0.3: U2.21 R11.1@47,4.983 ; R11.1 v3(48.113,4.988)
MISO1: R9.2 U1.6 U2.13 | length 48.1
  TopLayer w0.25: v1(34.075,-7.8) 34.075,-4.5 v1(34.55,-4.025) 37.25,-1.325 v1(40.55,-1.325)
  BottomLayer w0.25: U1.6 7.775,-9.475 10.4,-6.85 18.925,-6.85 21.75,-4.025 v1(34.55,-4.025) ; R9.2 v1(34.075,-7.8) ; v1(40.55,-1.325) 40.9,-0.975 U2.13
MOSI1: R6.2 U1.5 U2.14 | length 46.1
  TopLayer w0.25: v1(35.85,-7.725) v1(35.85,-4.7)
  BottomLayer w0.25: U1.5 9.045,-9.555 11.2,-7.4 19.35,-7.4 21.975,-4.775 35.875,-4.775 40.175,-0.475 U2.14 ; R6.2 v1(35.85,-7.725)
NetC5_2: C5.2 C9.2 FB3.2 | length 5.7
  BottomLayer w0.6: C9.2 15.099,7.361 C5.2 16.962,6.299 FB3.2
NetC15_1: C15.1 FB2.1 U7.1 | length 4
  BottomLayer w0.5: FB2.1 23.274,4.513 23.274,2.278 U7.1
NetC16_1: C16.1 R16.1 U2.2 Y1.1 | length 9.9
  BottomLayer w0.3: U2.2 49.5,-4.97 50.462,-5.932 R16.1
  BottomLayer w0.5: R16.1@50.751,-6.751 51.9,-7.9 Y1.1 52.437,-9.987 C16.1@52.437,-12.076
NetC17_1: C17.1 R3.2 U5.7 | length 11
  BottomLayer w0.3: U5.7 8.839,13.064 9.15,13.375 15.15,13.375 C17.1@16.293,14.518
  BottomLayer w0.6: C17.1@16.278,14.39 R3.2
NetC18_1: C18.1 R16.2 U2.3 Y1.2 | length 10.2
  BottomLayer w0.3: R16.2@49,-6.689 U2.3
  BottomLayer w0.5: C18.1@47.378,-12.099 47.378,-9.947 Y1.2 Y1.2@48.025,-8.814 ; Y1.2@47.838,-9.413 47.838,-7.851 R16.2@49,-6.689
NetC22_1: C22.1 U6.2 | length 3.6
  BottomLayer w0.3: U6.2 62.65,10.6 63.538,11.488 C22.1
NetC22_2: C22.2 D1.2 L1.1 U6.3 | length 11.4
  BottomLayer w0.3: U6.3 63.6,10.1 65.062,11.562 C22.2
  BottomLayer w0.8: L1.1 60.888,15.078 D1.2 65.062,14.373 C22.2
NetC23_1: C23.1 C51.1 FB7.1 L1.2 U6.1 U6.6 VR3.2 | length 28.9
  BottomLayer w0.3: 61.175,12.2 61.55,11.825 U6.1
  BottomLayer w0.4: VR3.2@52.787,14.526 52.787,13.687 51.975,12.875 51.975,9.75 52.625,9.1 U6.6 ; C23.1 55.625,13.175 56.6,12.2 61.175,12.2
  BottomLayer w0.8: FB7.1 48.965,14.563 C51.1 VR3.2 ; VR3.2@53.126,14.538 55.601,14.538 C23.1 58.164,14.514 L1.2
NetC29_2: C29.2 C30.1 R20.2 U5.5 | length 8.6
  BottomLayer w0.3: U5.5 7.539,12.811 7.05,13.3 5.675,13.3 5.201,13.774 C29.2 R20.2 8.45,16.022 C30.1
NetC30_2: C30.2 C31.1 R25.2 U5.6 | length 6.4
  BottomLayer w0.3: U5.6 8.189,13.936 C30.2 R25.2 12.259,14.498 C31.1
NetD3_2: D3.2 F13.2 L3.1 VR1.1 | length 8.7
  BottomLayer w1.5: F13.2 VR1.1 58.924,24.639 D3.2 L3.1@62.59,23.865
NetF10_1: F10.1 R41.2 T1.1 U12.13 U12.18 ZD14.1 ZD15.1 | length 29.5
  BottomLayer w0.5: U12.13 33.785,15.84 35.225,14.4 39.125,14.4 40.135,15.41 U12.18 40.135,20.236 R41.2 40.162,20.263 T1.1 ; T1.1@40.125,22.049 40.125,23.875 39.725,24.275 39.725,27.175 40.325,27.775 ZD14.1
  BottomLayer w0.6: ZD14.1@41.3,27.075 42.717,28.492 F10.1 43.997,25.028 ZD15.1
NetF11_1: F11.1 R42.1 R76.1 U12.15 U12.17 ZD14.2 ZD16.2 | length 25.6
  BottomLayer w0.5: ZD16.2 36,22.9 38.05,24.95 38.05,26.575 ZD14.2 ; R42.1 R42.1@35.275,20.352 ; R76.1 36.753,20.276 36.751,20.274 36.325,19.848 U12.15 36.325,15.8 36.825,15.3 38.425,15.3 38.865,15.74 U12.17
  BottomLayer w0.6: ZD16.2 35.197,21.728 R42.1 R76.1@36.751,20.274 ; F11.1 35.208,28.567 ZD14.2@36.7,27.075
NetLED2_1: LED2.1 R2.2 | length 30.2
  TopLayer w0.4: LED2.1 39.225,40.05 46.65,40.05 50,36.7 50,23.575 v1(51.224,22.351)
  BottomLayer w0.5: R2.2 v1(51.224,22.351)
NetP1_2: P1.2 R13.2 | length 1.8
  BottomLayer w0.6: P1.2 55.341,-0.423 R13.2
NetQ6_1: Q6.1 R11.2 | length 1.9
  BottomLayer w0.4: Q6.1 47.004,8.421 R11.2
NetR8_2: R8.2 U6.8 | length 3.1
  BottomLayer w0.3: R8.2 53.563,10.1 U6.8
NetR20_1: R20.1 U15.12 | length 7.2
  BottomLayer w0.3: R20.1 6.926,17.022 7.729,17.825 11.175,17.825 11.65,18.3 U15.12
NetR23_1: R23.1 U1.10 | length 12.4
  BottomLayer w0.3: U1.10 6.505,-3.88 7.075,-4.45 16.486,-4.45 R23.1
NetR25_1: R25.1 U15.11 | length 4.3
  BottomLayer w0.3: R25.1@10.475,16.048 R25.1 10.501,16.826 10.875,17.2 11.525,17.2 12.3,17.975 U15.11
NetR76_2: R76.2 T1.2 | length 1.8
  BottomLayer w0.5: R76.2 38.638,20.437 T1.2
PH-INP: J1.2 U15.5 | length 8.1
  BottomLayer w0.4: J1.2 11.65,33.655 U15.5
PH-VCM: J2.3 U15.8 | length 54.8
  BottomLayer w0.4: U15.8 15.375,25.6
  BottomLayer w0.5: 9.6,27 9.6,30.8 8.95,31.45 5.2,31.45 4.425,32.225 4.425,35.65 5.525,36.75 13.8,36.75 14.6,35.95 14.6,31.75 13.971,31.121 13.971,27.075 13.6,26.704 U15.8 13.6,23.975 12.975,23.35 10.7,23.35 9.975,24.075 9.975,24.5
  BottomLayer w0.6: 15.375,25.6 17.75,25.6 21.715,29.565 J2.3
RS485+: F10.2 J3.2 | length 4.9
  BottomLayer w0.6: J3.2 42.045,30.919 42.572,30.392 F10.2
RS485-: F11.2 J3.3 | length 5.4
  BottomLayer w0.6: F11.2 35.792,30.467 36.965,31.64 J3.3
RST#: C8.1 J9.15 R14.2 U2.4 | length 45.6
  TopLayer w0.3: v1(48.1,-5.155) 52.745,-5.155 v1(52.75,-5.15)
  BottomLayer w0.3: C8.1 45.012,-8.824 R14.2 45.037,-8.218 v1(48.1,-5.155) 48.5,-4.755 U2.4 ; v1(52.75,-5.15) 59.1,-5.15 64.075,-0.175 65.775,-0.175 70.65,4.7 74.5,4.7 77.645,7.845 J9.15
RX485: U2.10
SCK1: R10.2 U1.4 U2.12 | length 43.9
  TopLayer w0.3: v1(37.675,-7.8) 37.675,-6.125 v1(38.35,-5.45)
  BottomLayer w0.3: U1.4 10.315,-9.56 11.9,-7.975 19.6,-7.975 22.075,-5.5 38.325,-5.5 42.35,-1.475 U2.12 ; R10.2 v1(37.675,-7.8)
SPI_CS: U1.14 U5.3 | length 20
  BottomLayer w0.25: U5.3 6.239,9.539 4.35,7.65 4.35,3.125 5.775,1.7 9.525,1.7 11.585,-0.36 U1.14
SPI_DIN: U1.12 U5.16 | length 11.5
  TopLayer w0.25: v3(8.525,2.375) 9.025,1.875 v3@9.025,-0.175
  BottomLayer w0.25: U5.16 4.961,3.464 6.05,2.375 v3(8.525,2.375) ; v3(9.025,0) 9.045,-0.02 U1.12
SPI_DOUT: U1.11 U5.15 | length 9.2
  TopLayer w0.25: v3(6.525,3.125) 7.725,1.925 v3(7.725,-0.075)
  BottomLayer w0.25: U5.15 5.611,4.039 v3(6.525,3.125) ; U1.11@7.725,-2.129 U1.11 7.775,-0.125 v3(7.725,-0.075)
SPI_SCLK: U1.13 U5.1 | length 19.3
  BottomLayer w0.3: U5.1 4.939,9.114 3.775,7.95 3.775,2.775 5.525,1.025 9.1,1.025 10.315,-0.19 U1.13
SSEL1: R12.2 U1.3 U2.11 | length 41.7
  BottomLayer w0.25: U1.3 11.585,-9.64 12.575,-8.65 19.875,-8.65 22.3,-6.225 39.15,-6.225 39.5,-5.875 ; R12.2 39.5,-5.875 ; U2.11 43.4,-1.975 39.5,-5.875
TP+: J2.1 R3.1 R21.2 U5.11 | length 47.9
  BottomLayer w0.4: U5.11 8.211,8.886 9.85,10.525 17.825,10.525 22.175,14.875 22.175,19.975
  BottomLayer w0.6: R3.1 18.699,16.099 ; 18.699,16.499 22.175,19.975 23.662,21.462 R21.2 ; R21.2@23.7,25.525 J2.1
TX485: U2.9
VCC3.3: C1.1 C3.2 C10.1 C11.1 C12.1 C13.1 C43.1 C44.1 CA1.1 CA13.1 CA14.1 FB7.2 J9.1 J9.2 P3.1 P3V3.1 R1.1 R2.1 R4.1 R5.1 R6.1 R7.2 R9.1 R10.1 R12.1 R13.1 R14.1 R17.1 R22.1 U1.1 U2.1 U2.6 U2.19 U2.27 U12.2 U12.8 | length 218.5
  TopLayer w0.5: v1(74.851,17.976) 75.824,17.976
  TopLayer w0.6: 45.925,2.55 45.95,2.575 v1(45.95,3.425) ; 49.2,3.25 49.324,3.126 v1(52.525,3.126)
  TopLayer w0.8: v1(66.337,-8.838) v1@66.45,-8.725 ; v1(74.801,20.501) 75.85,19.452
  TopLayer w1: v1@34.036,0.636 40.139,0.636 40.311,0.636 41.576,1.901 ; P3V3.1 49.2,3.25 48.5,2.55 45.925,2.55 42.225,2.55 41.576,1.901 ; v1(57.999,-0.426) 57.074,-0.426 56.3,-1.2 56.3,-5.85 55.25,-6.9 ; v1@66.45,-8.725 66.45,-6.175 ; J9.2 J9.1 76.975,25.625 75.85,24.5 75.85,19.452 75.85,9.375 72.6,6.125 69.375,6.125 66.45,3.2 66.45,-6.175 ; 41.576,1.901 41.576,-7.849 v1(42.526,-8.799) 44.325,-7 49.186,-7 49.286,-6.9 55.25,-6.9 ; 55.25,-6.9 65.725,-6.9 66.45,-6.175
  BottomLayer w0.3: C11.1 47.5,-4.343 U2.6 ; C13.1 45.279,4.151 46,3.43 U2.19 ; FB7.2 47.086,11.939 46.525,12.5 46.525,13.525 46.163,13.887 R7.2 45.349,14.999 46.025,15.675 48.325,15.675 51.224,18.574 v1(51.224,18.799) ; U2.1 50,-3.85 v1(53.138,-6.988) C10.1 ; U2.27 50,2.85 50.276,3.126 v1(52.525,3.126) C12.1
  BottomLayer w0.5: U12.8 33.785,2.191 CA14.1 ; CA13.1@38.894,2.231 40.155,3.491 ; R14.1 43.513,-8.33 C11.1 ; v1(51.224,18.799) R2.1 ; R13.1 v1(57.999,-0.426) ; R1.1 v1(66.337,-8.838) ; v1(74.801,20.501) R5.1 R4.1 ; v1(74.851,17.976) R17.1 ; R22.1 v1(75.803,11.378)
  BottomLayer w0.6: U1.1 15.3,-11.45 16.012,-10.738 C1.1 C3.2 20.823,-9.214 CA1.1 ; 20.625,-9.214 26.164,-9.214 P3.1 29.2,-11.025 29.75,-10.475 v1(32.775,-10.475) R9.1 R6.1 R10.1 R12.1 40.3,-10.475 41.976,-8.799 v1(42.526,-8.799) R14.1 ; CA13.1 40.413,3.549 C43.1 40.413,4.913 41.405,5.905 U12.2
  BottomLayer w0.8: 16.012,-10.738 C1.1 ; v1(33.976,0.576) CA14.1 ; v1(38.889,0.636) CA13.1
  BottomLayer w1: CA14.1@33.725,1.749 CA14.1 ; FB7.2 49.2,11.364 P3V3.1
VCC_COM: C45.1 C46.2 CA15.1 CA16.1 R41.1 U12.12 U12.19 | length 32.3
  BottomLayer w0.5: CA15.1@26.3,16.039 CA15.1 26.701,16.013 29.437,16.013 29.875,15.575 32.15,15.575 ; U12.12 32.515,15.94 32.15,15.575 ; R41.1 41.405,19.982 U12.19 41.405,15.97 ; CA16.1 47.286,17.963 C46.2 44.826,16.676 43.475,15.325 42.05,15.325 41.405,15.97 ; 32.15,15.575 34.2,13.525 40.45,13.525 41.405,14.48 41.405,15.97
  other v1: 29.9,15.575 45.85,17.95 41.375,18.925
VDD_ISO: C2.1 C6.1 C14.1 C25.1 CA2.1 FB1.1 R23.2 U1.16 U5.13 U7.3 U15.1 U15.14 | length 64
  TopLayer w0.8: v1@6.4,18.55 8.45,16.5 ; 8.45,16.7 8.45,16.5 ; 8.45,17.1 9.8,18.45 v1(9.8,20.525) ; v1(16.675,1.3) 13.85,4.125 9.95,4.125 8.45,5.625 8.45,16.5
  BottomLayer w0.3: U5.13 6.911,4.914 7.75,4.075 v1(10.95,4.075) 11.511,4.075 C14.1
  BottomLayer w0.4: C25.1@6.313,25.6 U15.1 ; v1@6.4,18.475 6.4,20.575 5.175,21.8 5.175,25.25 5.537,25.612 C25.1 ; v1(9.8,20.525) 10.1,20.525 10.35,20.275 U15.14 ; CA2.1@15.336,1.4 CA2.1@15.336,1.814
  BottomLayer w0.5: CA2.1 15.336,1.248 14.125,0.037 U1.16 14.534,-2.588 R23.2 ; CA2.1@15.336,1.4 15.4,1.336 CA2.1@15.4,1.312 ; C6.1 C6.1@19.415,1.326 ; v1(19.75,2.675) 19.75,4.462 FB1.1 ; C6.1@19.774,1.545 v1@19.774,2.675 ; U7.3 U7.3@21.268,1.326
  BottomLayer w0.8: CA2.1@15.4,1.312 C2.1 C6.1 ; C6.1@19.415,1.326 U7.3@21.268,1.326
  other v1: 18.475,1.35 6.375,18.587
VREF: C33.1 C35.1 FB2.2 U5.9 U15.9 | length 28.4
  TopLayer w0.5: v1(15,16.05) 15,10.075 v1(16.075,9)
  BottomLayer w0.3: U5.9 9.511,7.161 10.125,7.775 C35.1@11.749,7.775
  BottomLayer w0.35: U15.9 13.6,17.551 14.026,17.126 C33.1
  BottomLayer w0.5: C35.1 13.013,7.763 14.25,9 20.925,9 21.524,8.401 FB2.2 ; C33.1 14.962,16.012 v1(15,16.05)
pads on no net: J9.11 J9.17 J9.19 P3.4 P4.1 P4.2 P4.3 P4.4 U1.7 U2.7 U2.15 U2.16 U2.20 U2.32 U2.33 U2.34 U5.2 U5.4 U6.7 U6.9 U15.2 U15.3 U15.7

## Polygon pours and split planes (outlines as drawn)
GND_ISO on TopLayer "BottomLayer-No Net" (hatched 90Degree grid 0.3 track 0.3, remove dead copper, pour order 6): 28.7,37.575 28.7,29.35 25.025,25.675 24.7,25.35 24.7,8.65 24.7,1.15 18.55,-5 -12.6,-5 -12.65,-4.95 -12.65,37.475 -12.8,37.625
VCC3.3 on TopLayer "BottomLayer-No Net" (hatched 90Degree grid 0.3 track 0.3, remove dead copper, pour order 9): 48.525,10.475 50.175,10.475 51.4,9.25 51.9,8.75 51.9,2.05 48.625,2.05 48.55,1.975
GND_COM on TopLayer "BottomLayer-No Net" (hatched 90Degree grid 0.3 track 0.3, remove dead copper, pour order 7): 27.825,12.6 41.1,12.6 45.425,16.925 46.55,18.05 46.55,21.975 27.875,21.975 27.825,21.925
GND on TopLayer "BottomLayer-No Net" (hatched 90Degree grid 0.3 track 0.3, remove dead copper, pour order 10): -3.525,-6.3 19.125,-6.3 22.925,-2.5 25.65,0.225 25.65,11.375 41.875,11.375 46.1,15.6 46.2,15.7 49.975,15.7 49.975,37.55 84.9,37.55 85.05,37.4 85.05,-13.55 84.725,-13.875 -3.35,-13.875 -3.525,-13.7
GND_ISO on BottomLayer "BottomLayer-No Net" (hatched 90Degree grid 0.3 track 0.3, remove dead copper, pour order 8): 24.425,20.8 -12.425,20.8 -12.575,20.95 -12.575,-4.8 18.5,-4.8 24.575,1.275 24.575,20.575 24.4,20.75
GND on BottomLayer "BottomLayer-No Net" (hatched 90Degree grid 0.3 track 0.3, remove dead copper, pour order 11): -3.6,-6.35 19.375,-6.35 25.725,0 25.725,11.3 25.85,11.425 42.15,11.425 45.7,14.975 46.15,15.425 50.275,15.425 50.325,15.475 50.325,37.4 50.7,37.775 85.025,37.775 84.775,37.525 84.775,-13.8 84.725,-13.85 -3.625,-13.85

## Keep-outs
KeepOutLayer:
  lines w0.3: 15.625,28.675 15.625,44.6 ; 15.65,28.675 ccw(c17.368,29.213) 19.086,28.675 ; 19.072,28.625 19.072,44.325 ; 23.5,28.7 23.5,45.925 ; 23.525,28.7 ccw(c24.138,28.892) 24.75,28.7 24.75,45.85
  lines w0.5: -7.735,-4.177 cw(c-7.88,-9.155) -2.902,-9.01 ; -7.735,-4.175 -12.6,-4.175 -12.6,33.825 -7.735,33.825 ; -7.735,33.827 ccw(c-7.88,38.805) -2.902,38.66 ; -2.925,-9.01 -2.925,-13.825 75.1,-13.825 75.1,-9.355 ; -2.9,38.66 -2.9,43.65 75.075,43.65 75.075,38.966 ; 75.102,-9.21 cw(c80.08,-9.355) 79.935,-4.377 ; 75.103,38.817 ccw(c80.216,38.966) 80.067,33.852 ; 80.08,-4.375 84.875,-4.375 84.875,33.85 80.216,33.85

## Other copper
TopLayer:
  pour cut-out: 3.95,44.25 3.95,31.825 9.75,31.825 10.05,31.525 10.05,23.8 10.875,22.975 14.2,22.975 15.675,24.45 15.675,44.25
BottomLayer:
  pour cut-out: 58.05,17.025 61.65,17.025 61.675,17 61.675,13.2 61.7,13.175 58.025,13.175

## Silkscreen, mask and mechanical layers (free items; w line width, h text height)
TopOverlay:
  lines w0.2: 27.38,-13.5 50,-13.5 50,26.595 27.38,26.595 27.38,-13.5
  text "- RS485 +   PE" at 35.45,28.375 h1
  text "+24V   GND   PE" at 50.175,28.275 h1
  text "VCM  - Temp +" at 20.9,28.175 h1
  text "GUARD  INP" at 4.9,28 h1
  text "SPLora module" at 30.375,11.9 h1
  text "SPMsensor_RS485 V0.2" at -5.825,7.975 h1.2 r90
  text "JTAG" at 76.325,5.525 h0.8 r270
BottomOverlay:
  lines w0.3: 3.475,17.325 16.725,17.325 16.725,29.375 3.475,29.375 3.475,17.325
Mechanical1:
  lines w0.2: 24.826,25.301 43.054,25.301
  lines w0.25: -14.675,30 75.525,30 ; -13.9,33.675 76.3,33.675 ; -13.65,0 87.15,0 ; -0.025,-4.875 -0.025,36.625 ; 72.45,-5.025 72.45,45.8
  lines w0.254: -13.425,43.65 86.675,43.65 ; -12.596,-13.814 87.914,-13.814 ; 6.475,26.45 6.475,42.85 ; 84.875,-12.675 84.875,46.95
  lines w0.3: -12.594,-18.55 -12.594,55.4 ; 29.2,-13.175 29.2,29.35 ; 55.7,-30.025 55.7,46.1

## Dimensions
2.675,17.326 to 2.692,23.3 on Mechanical1
16.789,17.379 to 17.2,19.9 on Mechanical1
40.297,-12.224 to 46.239,25.301 on Mechanical1
-14.225,15 to -13.625,0 on Mechanical1
-13.675,-13.816 to -14.65,15 on Mechanical1
-0.025,-3.2 to 72.45,-3.875 on Mechanical1
-12.596,-13.814 to 84.875,-12.675 on Mechanical1
-12.596,-13.814 to -13.425,43.65 on Mechanical1
6.475,42.325 to -0.025,36.625 on Mechanical1
-13.475,43.675 to -13.2,33.675 on Mechanical1
-14.225,30 to -13.625,15 on Mechanical1
3.686,29.321 to 3.625,17.325 on Mechanical1
3.475,17.592 to 16.747,17.814 on Mechanical1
